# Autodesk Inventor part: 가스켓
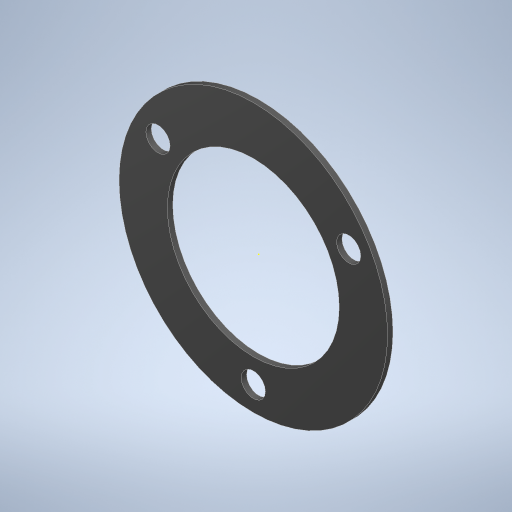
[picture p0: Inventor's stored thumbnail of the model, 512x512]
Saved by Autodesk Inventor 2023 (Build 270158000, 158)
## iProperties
Created: 2025-10
Part Number: 가스켓
Material: 스테인리스스틸
Document SubType Name: Modeling
Designer: home
Density: 8 g/cm^3
Appearance: 기본값
Author: jhkim
Sending System: Autodesk Inventor 2026
Preprocessor: ST-DEVELOPER v20.1
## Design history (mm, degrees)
sketch "스케치1"
  geometry: 1 further point
  constraints: 1 other
feature "솔리드1"
node "솔리드2"
